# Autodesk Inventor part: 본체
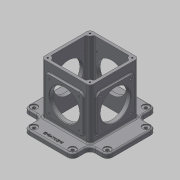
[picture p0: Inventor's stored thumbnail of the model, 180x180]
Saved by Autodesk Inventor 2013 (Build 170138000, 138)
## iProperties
Created: 2018-09
Part Number: 본체
Material: 일반
Document SubType Name: Modeling
Designer: mduedu
Density: 1 g/cm^3
Mass: 415.736 g
Surface Area: 1144.86 cm^2
Volume: 415.736 cm^3
Author: mduedu
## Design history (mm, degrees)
sketch "스케치1"
  geometry: L1 (90, 52.5)-(-90, 52.5); L2 (-90, 52.5)-(-90, -52.5); L3 (-90, -52.5)-(90, -52.5); L4 (90, -52.5)-(90, 52.5); L5 (90, 52.5)-(-90, -52.5); L6 (-90, 52.5)-(90, -52.5); L7 (-52.5, -90)-(52.5, -90); L8 (52.5, -90)-(52.5, 90); L9 (52.5, 90)-(-52.5, 90); L10 (-52.5, 90)-(-52.5, -90); L11 (-52.5, -90)-(52.5, 90); L12 (52.5, -90)-(-52.5, 90); 1 further point
  constraints: 24 end point, 4 midpoint, 4 parallel, 2 horizontal, 2 perpendicular
  dimensions: "d0" = 180 distance of L3.end L2.end; "d1" = 105 distance of L2.end L1.end; "d105" = 105 distance of L9.end L8.end; "d106" = 180 distance of L8.end L7.end
extrude "돌출1" new body sketch "스케치1" distance "d2" = 10; taper "d3" = 0 deg
fillet "모깎기16" dims "d107" = 11
sketch "스케치2"
  geometry: L1 (-52.5, -52.5)-(52.5, -52.5); L2 (52.5, -52.5)-(52.5, 52.5); L3 (52.5, 52.5)-(-52.5, 52.5); L4 (-52.5, 52.5)-(-52.5, -52.5); L5 (-52.5, -52.5)-(52.5, 52.5); L6 (52.5, -52.5)-(-52.5, 52.5); 1 further point
  constraints: 12 end point, 2 midpoint, 2 parallel, 1 horizontal, 1 perpendicular
  dimensions: "d4" = 105 distance of L3.end L2.end; "d5" = 105 distance of L2.end L1.end
extrude "돌출2" join sketch "스케치2" distance "d6" = 110; taper "d7" = 0 deg
sketch "스케치14"
  geometry: L1 (-52.5, 52.5)-(52.5, 52.5) reference; L2 (52.5, 52.5)-(52.5, -52.5) reference; L3 (52.5, -52.5)-(-52.5, -52.5) reference; L4 (-52.5, -52.5)-(-52.5, 52.5) reference; L5 (46.5, 46.5)-(-46.5, 46.5); L6 (-46.5, 46.5)-(-46.5, -46.5); L7 (-46.5, -46.5)-(46.5, -46.5); L8 (46.5, -46.5)-(46.5, 46.5); 1 further point
  constraints: 8 end point, 3 other
  dimensions: "d85" = 6 distance between parallel lines of L5 L1
extrude "돌출10" cut sketch "스케치14" stored distance "d86" = 10; taper "d87" = 0 deg
fillet "모깎기1" dims "d12" = 7
sketch "스케치15"
  geometry: A1 r 7 centre (-45.5, 45.5) between (-45.5, 52.5) and (-52.5, 45.5) reference; A2 r 7 centre (45.5, 45.5) between (52.5, 45.5) and (45.5, 52.5) reference; A3 r 7 centre (45.5, -45.5) between (45.5, -52.5) and (52.5, -45.5) reference; A4 r 7 centre (-45.5, -45.5) between (-52.5, -45.5) and (-45.5, -52.5) reference; 5 further points
  constraints: 4 coincident, 4 vertical alignment, 8 other
extrude "돌출11" join sketch "스케치15" stored distance "d88" = 10; taper "d89" = 0 deg
fillet "모깎기15" dims "d90" = 3
sketch "스케치6"
  geometry: L1 (50, 20)-(130, 20); L2 (130, 20)-(130, 100); L3 (130, 100)-(50, 100); L4 (50, 100)-(50, 20); L5 (50, 20)-(130, 100); L6 (130, 20)-(50, 100); L7 (0, 0)-(180, 0) reference; 4 further points
  constraints: 12 end point, 4 midpoint, 2 parallel, 1 horizontal, 1 perpendicular, 1 vertical alignment
  dimensions: "d25" = 80 distance of L3.end L2.end; "d26" = 80 distance of L2.end L1.end; "d27" = 60 distance of point (90, 0) point (90, 60)
extrude "돌출6" join sketch "스케치6" distance "d28" = 3; taper "d29" = 0 deg
fillet "모깎기7" dims "d30" = 8
sketch "스케치7"
  geometry: C1 r 32.5 at (90, 60); 1 further point
  constraints: 1 centre point, 1 vertical alignment
  dimensions: "d32" = 65 diameter of C1; "d33" = 60 distance of C1.centre point (90, 0)
extrude "돌출7" cut sketch "스케치7" stored distance "d34" = 3; taper "d35" = 0 deg
fillet "모깎기9" dims "d36" = 3
sketch "스케치8"
  geometry: L1 (5.5, 10)-(85.5, 10); L2 (85.5, 10)-(85.5, 90); L3 (85.5, 90)-(5.5, 90); L4 (5.5, 90)-(5.5, 10); L5 (5.5, 10)-(85.5, 90); L6 (85.5, 10)-(5.5, 90); L7 (-7, -10)-(98, -10) reference; C1 r 32.5 at (45.5, 50); 4 further points
  constraints: 12 end point, 4 midpoint, 2 parallel, 1 centre point, 1 coincident, 1 horizontal, 1 perpendicular, 1 vertical alignment
  dimensions: "d37" = 80 distance of L3.end L2.end; "d38" = 80 distance of L2.end L1.end; "d39" = 60 distance from line of point (45.5, 50) L7; "d40" = 65 diameter of C1
extrude "돌출8" join sketch "스케치8" distance "d41" = 3; taper "d42" = 0 deg
fillet "모깎기10" dims "d43" = 8
extrude "돌출9" cut sketch "스케치8" stored distance "d44" = 3; taper "d45" = 0 deg
fillet "모깎기11" dims "d46" = 3
sketch "스케치9"
  geometry: L1 (50, 92)-(50, 28) reference; L2 (58, 20)-(122, 20) reference; L3 (130, 28)-(130, 92) reference; L4 (122, 100)-(58, 100) reference; C1 r 32.5 at (90, 60) reference; A1 r 8 centre (58, 92) between (58, 100) and (50, 92) reference; A2 r 8 centre (58, 28) between (50, 28) and (58, 20) reference; A3 r 8 centre (122, 28) between (122, 20) and (130, 28) reference; A4 r 8 centre (122, 92) between (130, 92) and (122, 100) reference; 5 further points
  constraints: 4 coincident
hole "구멍1" sketch "스케치9" at (58, 92), (122, 92), (122, 28), (58, 28) diameter "d47" = 3.242; stored, may be unused: countersink angle "d51" = 90 deg, drill point angle "d53" = 118 deg; dims "d48" = 6, "d49" = 4, "d50" = 2, "d52" = 9
sketch "스케치10"
  geometry: L1 (13.5, 10)-(77.5, 10) reference; L2 (85.5, 18)-(85.5, 82) reference; L3 (77.5, 90)-(13.5, 90) reference; L4 (5.5, 82)-(5.5, 18) reference; C1 r 32.5 at (45.5, 50) reference; A1 r 8 centre (13.5, 18) between (5.5, 18) and (13.5, 10) reference; A2 r 8 centre (77.5, 18) between (77.5, 10) and (85.5, 18) reference; A3 r 8 centre (77.5, 82) between (85.5, 82) and (77.5, 90) reference; A4 r 8 centre (13.5, 82) between (13.5, 90) and (5.5, 82) reference; 5 further points
  constraints: 4 coincident
hole "구멍2" sketch "스케치10" at (13.5, 82), (77.5, 82), (77.5, 18), (13.5, 18) diameter "d54" = 3.242; stored, may be unused: countersink angle "d58" = 90 deg, drill point angle "d60" = 118 deg; dims "d55" = 6, "d56" = 4, "d57" = 2, "d59" = 9
fillet "모깎기12" dims "d68" = 11
sketch "스케치16"
  geometry: A1 r 11 centre (-79, 41.5) between (-79, 52.5) and (-90, 41.5) reference; A2 r 11 centre (-79, -41.5) between (-90, -41.5) and (-79, -52.5) reference; A3 r 11 centre (79, 41.5) between (90, 41.5) and (79, 52.5) reference; A4 r 11 centre (79, -41.5) between (79, -52.5) and (90, -41.5) reference; A5 r 11 centre (-41.5, 79) between (-41.5, 90) and (-52.5, 79) reference; A6 r 11 centre (41.5, 79) between (52.5, 79) and (41.5, 90) reference; A7 r 11 centre (41.5, -79) between (41.5, -90) and (52.5, -79) reference; A8 r 11 centre (-41.5, -79) between (-52.5, -79) and (-41.5, -90) reference; 9 further points
  constraints: 8 coincident
hole "구멍5" sketch "스케치16" at (-79, 41.5), (79, 41.5), (79, -41.5), (-79, -41.5), (41.5, 79), (-41.5, 79), (-41.5, -79), (41.5, -79) diameter "d91" = 6.6; stored, may be unused: countersink angle "d95" = 90 deg, drill point angle "d97" = 118 deg; dims "d92" = 6, "d93" = 15, "d94" = 2, "d96" = 8
fillet "모깎기13" dims "d77" = 3
chamfer "모따기1" distance "d79" = 1; stored, may be unused: second distance "d80" = 2, angle "d81" = 45 deg
sketch "스케치17"
  geometry: A1 r 7 centre (-45.5, 45.5) between (-45.5, 52.5) and (-52.5, 45.5) reference; A2 r 7 centre (-45.5, -45.5) between (-52.5, -45.5) and (-45.5, -52.5) reference; A3 r 7 centre (45.5, -45.5) between (45.5, -52.5) and (52.5, -45.5) reference; A4 r 7 centre (45.5, 45.5) between (52.5, 45.5) and (45.5, 52.5) reference; 5 further points
  constraints: 4 coincident
hole "구멍6" sketch "스케치17" at (-45.5, 45.5), (45.5, 45.5), (45.5, -45.5), (-45.5, -45.5) diameter "d98" = 3.242; stored, may be unused: countersink angle "d102" = 90 deg, drill point angle "d104" = 118 deg; dims "d99" = 8, "d100" = 15, "d101" = 2, "d103" = 10
sketch "스케치13"
  geometry: L1 (90, -41.5)-(90, 41.5) reference; 2 further points
  constraints: 1 horizontal alignment, 1 other
  dimensions: "d82" = 11 distance from line of point (79, 0) L1
feature "엠보싱1" sketch "스케치13" dims "d0" = 180, "d1" = 105, "d83" = 0.5, "d84" = 0
node "솔리드1"
mirror "대칭1"
mirror "대칭4"
mirror "대칭2"
mirror "대칭5"
node "투영된 루프2"
node "투영된 루프3"
node "투영된 루프6"
